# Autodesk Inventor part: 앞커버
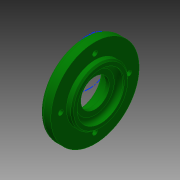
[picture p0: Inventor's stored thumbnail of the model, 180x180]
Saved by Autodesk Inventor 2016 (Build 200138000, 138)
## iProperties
Created: 2015-09
Part Number: 앞커버
Material: 알루미늄 6061
Document SubType Name: Modeling
Designer: mduedu
Density: 2.71 g/cm^3
Mass: 58.9874 g
Surface Area: 98.7754 cm^2
Volume: 21.7666 cm^3
Appearance: 진녹색
Author: mduedu
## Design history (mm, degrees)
sketch "스케치1"
  geometry: L1 (-8, 67)-(-12, 67); L2 (-12, 67)-(-12, 78); L3 (-12, 78)-(-20, 78); L4 (-20, 78)-(-20, 66); L5 (-23, 66)-(-23, 57); L6 (-23, 57)-(-8, 57); L7 (-8, 57)-(-8, 67); L8 (-79.5, 39.5)-(-79.5, 54.5) reference; L9 (48.5, 54.5)-(48.5, 39.5) reference; L10 (-79.5, 47)-(48.5, 47); L11 (-20, 66)-(-23, 66); 3 further points
  constraints: 18 end point, 6 parallel, 4 midpoint, 1 horizontal, 1 perpendicular, 1 vertical alignment
  dimensions: "d0" = 15 distance between parallel lines of L7 L5; "d2" = 20 diameter of L6 L10; "d3" = 40 diameter of L1 L10; "d5" = 4 distance of L1.start L1.end; "d6" = 62 diameter of L3 L10; "d7" = 8 distance of L2.end L3.end; "d8" = 38 diameter of L4.end L10
revolve "회전1" sketch "스케치1" stored, may be unused: angle "d4" = 90 deg
sketch "스케치2"
  geometry: C1 r 31 at (0, 0) reference; 2 further points
  constraints: 1 coincident
hole "구멍1" sketch "스케치2" at (0, 0) diameter "d11" = 33; stored, may be unused: countersink angle "d15" = 90 deg, drill point angle "d17" = 0 deg; dims "d12" = 6, "d13" = 4, "d14" = 2, "d16" = 4
fillet "모깎기1" dims "d18" = 3
fillet "모깎기2" dims "d19" = 1, "d60" = 3
sketch "스케치3"
  geometry: C1 r 31 at (0, 0) reference; 2 further points
  constraints: 1 coincident
hole "구멍2" sketch "스케치3" at (0, 0) diameter "d20" = 30; stored, may be unused: countersink angle "d24" = 90 deg, drill point angle "d26" = 0 deg; dims "d21" = 6, "d22" = 4, "d23" = 2, "d25" = 8.3
fillet "모깎기3" dims "d27" = 0.3
chamfer "모따기1" distance "d28" = 0.8; stored, may be unused: second distance "d29" = 2, angle "d30" = 30 deg
sketch "스케치4" dims "d31" = 56
  geometry: C1 r 31 at (0, 0) reference; 6 further points
  constraints: 2 vertical alignment, 1 coincident, 7 other
  dimensions: "d36" = 360 deg dimension on C1.centre point (0, 28) (derived)
sketch "스케치7"
  geometry: C1 r 30.5 at (0, 0) reference; A1 r 24 centre (0, 0) between (24, 0) and (0, 24); 2 further points
  constraints: 4 point on circle, 2 horizontal alignment, 2 vertical alignment, 1 centre point, 1 coincident
  dimensions: "d58" = 48 diameter of A1
hole "구멍4" sketch "스케치7" at (0, 24), (-24, 0), (24, 0), (0, -24) diameter "d48" = 3.4; stored, may be unused: countersink angle "d52" = 90 deg, drill point angle "d54" = 0 deg; dims "d49" = 6, "d50" = 6.5, "d51" = 3.4, "d53" = 8
chamfer "모따기2" distance "d55" = 1; stored, may be unused: second distance "d56" = 2, angle "d57" = 45 deg
node "솔리드1"
node "참조1"
node "참조2"
node "참조3"
